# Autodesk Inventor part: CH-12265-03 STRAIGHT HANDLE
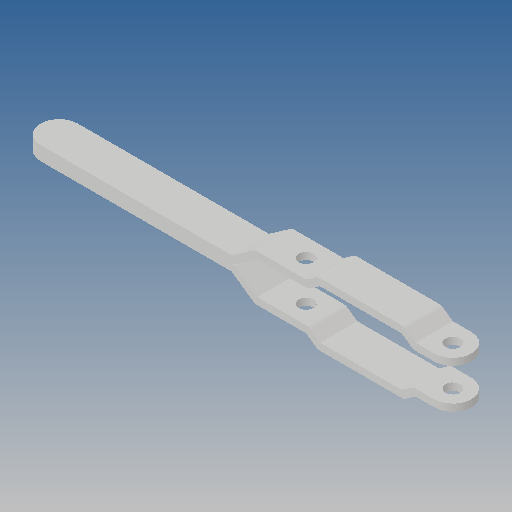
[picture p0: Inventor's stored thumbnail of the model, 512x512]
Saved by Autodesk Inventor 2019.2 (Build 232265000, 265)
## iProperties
Created: 2012-09
Part Number: CH-12265-03 STRAIGHT HANDLE
Material: Ogólny
Document SubType Name: Modeling
Designer: CADENGINEERING4
Density: 1 g/cm^3
Appearance: Domyślna
Author: CADENGINEERING4
Revision Number: ÈÎºÎ
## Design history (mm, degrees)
feature "ÇÐ³ý-À­Éì1"
feature "¾µÏò1"
node "Bryła1"
node "Bryła2"
